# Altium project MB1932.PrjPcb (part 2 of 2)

## Sheet STLINK_V2EC.SchDoc: STLINK-V2EC
size A3; Date: Not used; ApprovedBy: Not used; CheckedBy: Not used; Author: Not used; CompanyName: STMicroelectronics; DrawnBy: Not used; Engineer: Not used; Organization: Not used; Address1: Not used; Address2: Not used; Address3: Not used; Address4: Not used; DocumentNumber: Not used; Revision: V0.1; SheetNumber: 6; SheetTotal: 7
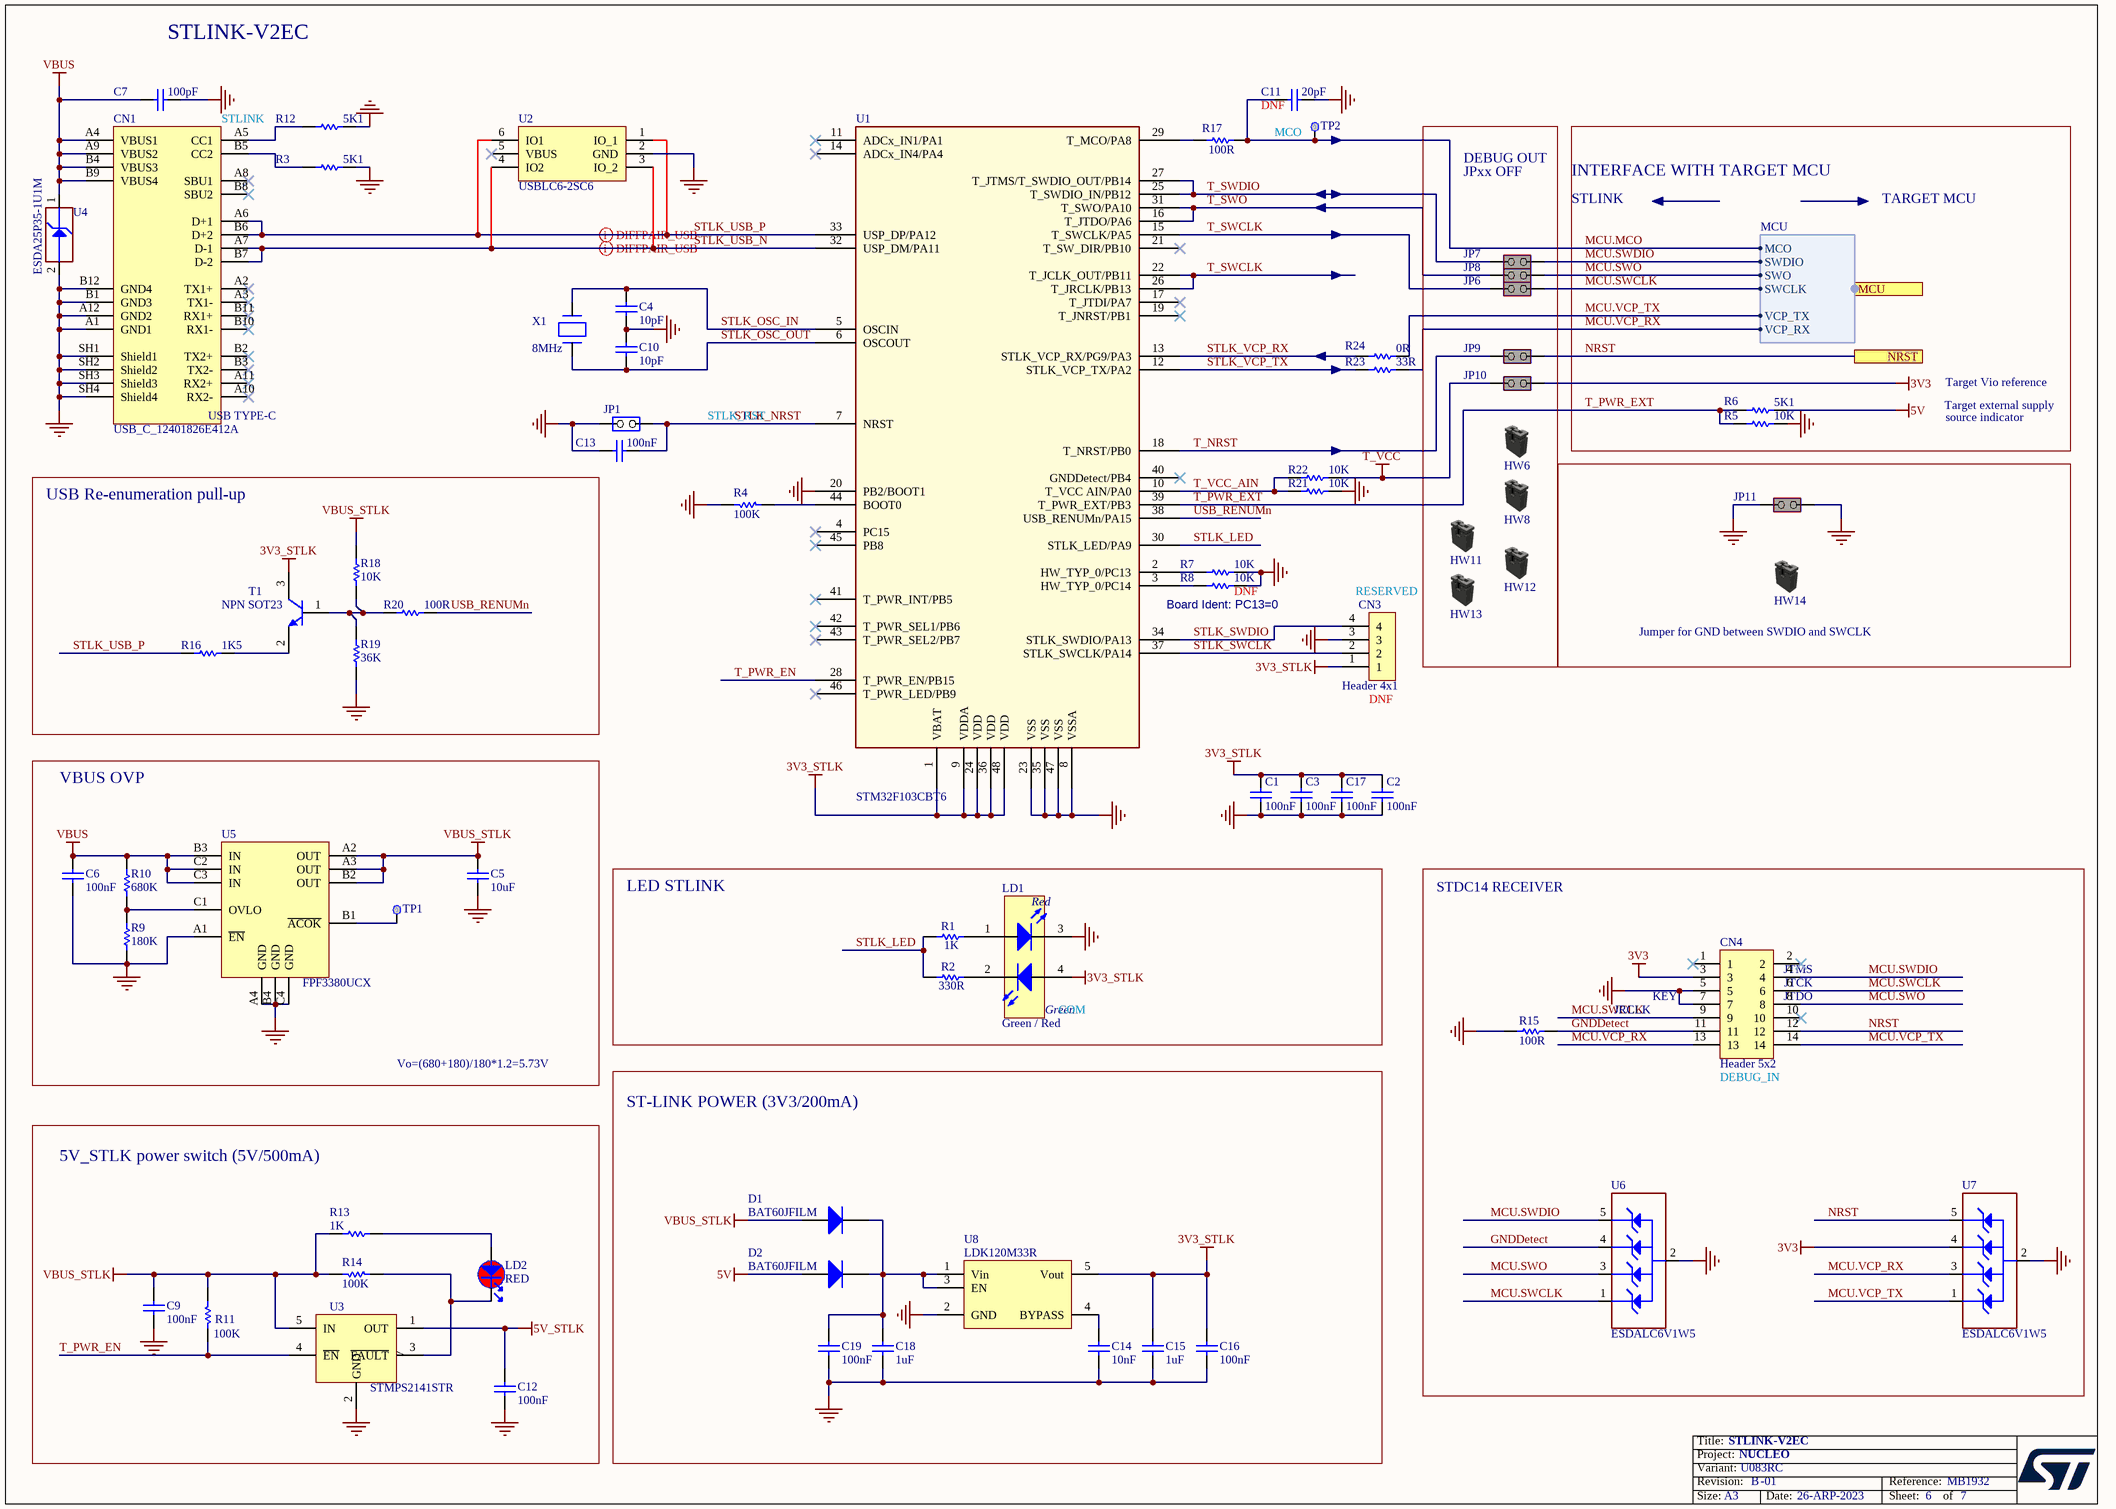
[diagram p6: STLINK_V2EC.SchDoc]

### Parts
C1  value 100nF  [C0402]  (hidden comment: Capacitor)
C2  value 100nF  [C0402]  (hidden comment: Capacitor)
C3  value 100nF  [C0402]  (hidden comment: Capacitor)
C4  value 10pF  [C0402]  (hidden comment: Capacitor)
C5  value 10uF  [C0603]  (hidden comment: Capacitor)
C6  value 100nF  [C0603]  (hidden comment: Capacitor)
C7  value 100pF  [C0402]  (hidden comment: Capacitor)
C9  value 100nF  [C0402]  (hidden comment: Capacitor)
C10  value 10pF  [C0402]  (hidden comment: Capacitor)
C11  value 20pF  [C0402]  (hidden comment: Capacitor)
C12  value 100nF  [C0402]  (hidden comment: Capacitor)
C13  value 100nF  [C0402]  (hidden comment: Capacitor)
C14  value 10nF  [C0402]  (hidden comment: Capacitor)
C15  value 1uF  [C0603]  (hidden comment: Capacitor)
C16  value 100nF  [C0402]  (hidden comment: Capacitor)
C17  value 100nF  [C0402]  (hidden comment: Capacitor)
C18  value 1uF  [C0603]  (hidden comment: Capacitor)
C19  value 100nF  [C0402]  (hidden comment: Capacitor)
CN1  value USB_C_12401826E412A  [CON_USB-TYPEC_AMPHENOL_12401826E412A]  (hidden comment: USB_TYPE_C_Receptacle)
CN3  Header 4x1  [CON_SAMTEC_TSW-104-07-G-S]
CN4  value Header 5x2  [CON_STDC14_Receiver_MEDIUM_WITH_MIPI10_3D]  (hidden comment: Header 7x2)
D1  BAT60JFILM  [DIO_SOD323]
D2  BAT60JFILM  [DIO_SOD323]
HW6  Shunt Black 2.54mm  (value not drawn)  (mechanical)
HW8  Shunt Black 2.54mm  (value not drawn)  (mechanical)
HW11  Shunt Black 2.54mm  (value not drawn)  (mechanical)
HW12  Shunt Black 2.54mm  (value not drawn)  (mechanical)
HW13  Shunt Black 2.54mm  (value not drawn)  (mechanical)
HW14  Shunt Black 2.54mm  (value not drawn)  (mechanical)
JP1  Jumper_Header 2x1  [CON_SAMTEC_TSW-102-07-G-S]  (value not drawn)
JP6  Jumper_Header 2x1 Fitted  [CON_SAMTEC_TSW-102-07-G-S]  (value not drawn)
JP7  Jumper_Header 2x1 Fitted  [CON_SAMTEC_TSW-102-07-G-S]  (value not drawn)
JP8  Jumper_Header 2x1 Fitted  [CON_SAMTEC_TSW-102-07-G-S]  (value not drawn)
JP9  Jumper_Header 2x1 Fitted  [CON_SAMTEC_TSW-102-07-G-S]  (value not drawn)
JP10  Jumper_Header 2x1 Fitted  [CON_SAMTEC_TSW-102-07-G-S]  (value not drawn)
JP11  Jumper_Header 2x1 Fitted  [CON_SAMTEC_TSW-102-07-G-S]  (value not drawn)
LD1  value Green / Red  [LED_BI-GR_WE-150141SV73110]  (hidden comment: LED_BICOLOR)
LD2  value RED  [LED_0402_KINGBRIGHT_KPHHS-1005SURCK_HYPER-RED_1A2K_H0P5]  (hidden comment: LED_red)
R1  value 1K  [R0402]  (hidden comment: Resistor)
R2  value 330R  [R0402]  (hidden comment: Resistor)
R3  value 5K1  [R0402]  (hidden comment: Resistor)
R4  value 100K  [R0402]  (hidden comment: Resistor)
R5  value 10K  [R0402]  (hidden comment: Resistor)
R6  value 5K1  [R0402]  (hidden comment: Resistor)
R7  value 10K  [R0402]  (hidden comment: Resistor)
R8  value 10K  [R0402]  (hidden comment: Resistor)
R9  value 180K  [R0402]  (hidden comment: Resistor)
R10  value 680K  [R0402]  (hidden comment: Resistor)
R11  value 100K  [R0402]  (hidden comment: Resistor)
R12  value 5K1  [R0402]  (hidden comment: Resistor)
R13  value 1K  [R0402]  (hidden comment: Resistor)
R14  value 100K  [R0402]  (hidden comment: Resistor)
R15  value 100R  [R0402]  (hidden comment: Resistor)
R16  value 1K5  [R0402]  (hidden comment: Resistor)
R17  value 100R  [R0402]  (hidden comment: Resistor)
R18  value 10K  [R0402]  (hidden comment: Resistor)
R19  value 36K  [R0402]  (hidden comment: Resistor)
R20  value 100R  [R0402]  (hidden comment: Resistor)
R21  value 10K  [R0402]  (hidden comment: Resistor)
R22  value 10K  [R0402]  (hidden comment: Resistor)
R23  value 33R  [R0402]  (hidden comment: Resistor)
R24  value 0R  [R0402]  (hidden comment: Resistor)
T1  value NPN SOT23  [NPN_SOT23]  (hidden comment: 9013-SOT23)
TP1  Test Point  [TP_SMD_1MM]  (value not drawn)  (no BOM)
TP2  Test Point  [TP_SMD_1MM]  (value not drawn)  (no BOM)
U1  value STM32F103CBT6  [ICC_LQFP48_7X7_P050]  (hidden comment: STLINK-V2EC)
U2  USBLC6-2SC6  [ESD_SOT23-6L]
U3  STMPS2141STR  [MOS_SOT23-5L]
U4  value ESDA25P35-1U1M  [ESD_QFN1610_2N_1K_2A]  (hidden comment: ESD-TRANSIL)
U5  FPF3380UCX  [ICC_WLCSP12_1P858x1P318_P040]
U6  ESDALC6V1W5  [ESD_SOT323-5L]
U7  ESDALC6V1W5  [ESD_SOT323-5L]
U8  LDK120M33R  [REG_SOT23-5L]
X1  value 8MHz  [CRY_NX3225GD_2P]  (hidden comment: XTAL_2_PINS)

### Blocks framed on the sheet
INTERFACE WITH TARGET MCU: R5 R6
USB Re-enumeration pull-up: R16 R18-R20 T1
Jumper for GND between SWDIO and SWCLK: HW14 JP11
VBUS OVP: C5 C6 R9 R10 TP1 U5
LED STLINK: LD1 R1 R2
STDC14 RECEIVER: CN4 R15 U6 U7
ST-LINK POWER (3V3/200mA): C14-C16 C18 C19 D1 D2 U8
5V_STLK power switch (5V/500mA): C9 C12 LD2 R11 R13 R14 U3

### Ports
MCU (harness MCU), NRST

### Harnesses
MCU: MCO, SWDIO, SWO, VCP_TX, SWCLK, VCP_RX

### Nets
3V3: CN4.3 JP10.1(COMMON) U7.4(IO3)
3V3_STLK: C1.1 C2.1 C3.1 C15.2 C16.2 C17.1 CN3.1 LD1.4(Green_anode) T1.3(C) U1.1(VBAT) U1.9(VDDA) U1.24(VDD) U1.36(VDD) U1.48(VDD) U8.5(Vout)
5V: D2.1(A) R6.2
5V_STLK: C12.2 U3.1(OUT)
GND: C1.2 C2.2 C3.2 C4.1 C5.1 C6.2 C7.2 C9.1 C10.2 C11.1 C12.1 C13.1 C14.1 C15.1 C16.1 C17.2 C18.1 C19.1 CN1.A1(GND1) CN1.A12(GND2) CN1.B1(GND3) CN1.B12(GND4) CN1.SH1(Shield1) CN1.SH2(Shield2) CN1.SH3(Shield3) CN1.SH4(Shield4) CN3.3 CN4.5 CN4.7 JP1.2(NO) JP11.1(COMMON) JP11.2(NO) LD1.3(RED_cathode) R3.2 R4.1 R5.2 R7.2 R8.2 R9.1 R12.2 R15.1 R19.1 R21.2 U1.8(VSSA) U1.20(PB2/BOOT1) U1.23(VSS) U1.35(VSS) U1.47(VSS) U2.2(GND) U3.2(GND) U4.2(GND) U5.A1(~{EN}) U5.A4(GND) U5.B4(GND) U5.C4(GND) U6.2(GND) U7.2(GND) U8.2(GND)
T_VCC: JP10.2(NO) R22.2
VBUS: C6.1 C7.1 CN1.A4(VBUS1) CN1.A9(VBUS2) CN1.B4(VBUS3) CN1.B9(VBUS4) R10.2 U4.1(IO1) U5.B3(IN) U5.C2(IN) U5.C3(IN)
VBUS_STLK: C5.2 C9.2 D1.1(A) R11.2 R13.2 R14.2 R18.2 U3.5(IN) U5.A2(OUT) U5.A3(OUT) U5.B2(OUT)
GNDDetect: CN4.11 R15.2 U6.4(IO3)
MCU.MCO: C11.2 R17.2 TP2.1 ; port MCU.MCO
MCU.SWCLK: CN4.6 CN4.9 JP6.1(COMMON) U6.1(IO1) ; port MCU.SWCLK
MCU.SWDIO: CN4.4 JP7.1(COMMON) U6.5(IO4) ; port MCU.SWDIO
MCU.SWO: CN4.8 JP8.1(COMMON) U6.3(IO2) ; port MCU.SWO
MCU.VCP_RX: CN4.13 R23.2 U7.3(IO2) ; port MCU.VCP_RX
MCU.VCP_TX: CN4.14 R24.2 U7.1(IO1) ; port MCU.VCP_TX
NRST: CN4.12 JP9.1(COMMON) U7.5(IO4) ; port NRST
STLK_LED: R1.2 R2.1 U1.30(STLK_LED/PA9)
STLK_NRST: C13.2 JP1.1(COMMON) U1.7(NRST)
STLK_OSC_IN: C4.2 U1.5(OSCIN) X1.2(X2)
STLK_OSC_OUT: C10.1 U1.6(OSCOUT) X1.1(X1)
STLK_SWCLK: CN3.2 U1.37(STLK_SWCLK/PA14)
STLK_SWDIO: CN3.4 U1.34(STLK_SWDIO/PA13)
STLK_USB_N: CN1.A7(D-1) CN1.B7(D-2) U1.32(USP_DM/PA11) U2.3(IO_2) U2.4(IO2)
STLK_USB_P: CN1.A6(D+1) CN1.B6(D+2) R16.1 U1.33(USP_DP/PA12) U2.1(IO_1) U2.6(IO1)
STLK_VCP_RX: R24.1 U1.13(STLK_VCP_RX/PG9/PA3)
STLK_VCP_TX: R23.1 U1.12(STLK_VCP_TX/PA2)
T_NRST: JP9.2(NO) U1.18(T_NRST/PB0)
T_PWR_EN: R11.1 U1.28(T_PWR_EN/PB15) U3.4(~{EN})
T_PWR_EXT: R5.1 R6.1 U1.39(T_PWR_EXT/PB3)
T_SWCLK: JP6.2(NO) U1.15(T_SWCLK/PA5) U1.22(T_JCLK_OUT/PB11) U1.26(T_JRCLK/PB13)
T_SWDIO: JP7.2(NO) U1.25(T_SWDIO_IN/PB12) U1.27(T_JTMS/T_SWDIO_OUT/PB14)
T_SWO: JP8.2(NO) U1.16(T_JTDO/PA6) U1.31(T_SWO/PA10)
T_VCC_AIN: R21.1 R22.1 U1.10(T_VCC_AIN/PA0)
USB_RENUMn: R20.2 U1.38(USB_RENUMn/PA15)
NetC14_2: C14.2 U8.4(BYPASS)
NetC18_2: C18.2 C19.2 D1.2(K) D2.2(K) U8.1(Vin) U8.3(EN)
NetCN1_A5: CN1.A5(CC1) R12.1
NetCN1_B5: CN1.B5(CC2) R3.1
NetLD1_1: LD1.1(Red_anode) R1.1
NetLD1_2: LD1.2(Green_cathode) R2.2
NetLD2_1: LD2.1 R13.1
NetLD2_2: LD2.2 R14.1 U3.3(~{FAULT})
NetR4_2: R4.2 U1.44(BOOT0)
NetR7_1: R7.1 U1.2(HW_TYP_0/PC13)
NetR8_1: R8.1 U1.3(HW_TYP_0/PC14)
NetR9_2: R9.2 R10.1 U5.C1(OVLO)
NetR16_2: R16.2 T1.2(E)
NetR17_1: R17.1 U1.29(T_MCO/PA8)
NetR18_1: R18.1 R19.2 R20.1 T1.1(B)
NetTP1_1: TP1.1 U5.B1(~{ACOK})

Not connected (* = marked no-connect by the designer): CN1 A2(TX1+)* A3(TX1-)* A8(SBU1)* A10(RX2-)* A11(RX2+)* B2(TX2+)* B3(TX2-)* B8(SBU2)* B10(RX1-)* B11(RX1+)*; CN4 1* 2* 10*; U1 4(PC15)* 11(ADCx_IN1/PA1)* 14(ADCx_IN4/PA4)* 17(T_JTDI/PA7)* 19(T_JNRST/PB1)* 21(T_SW_DIR/PB10)* 40(GNDDetect/PB4)* 41(T_PWR_INT/PB5)* 42(T_PWR_SEL1/PB6)* 43(T_PWR_SEL2/PB7)* 45(PB8)* 46(T_PWR_LED/PB9)*; U2 5(VBUS)*

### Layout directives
differential pair; rule Impedance Constraint [Min = 85.00    Max = 95.00    ]: STLK_USB_N, STLK_USB_P

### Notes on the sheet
- STLINK-V2EC
- (near C11) DNF
- STLINK
- MCO
- JPxx OFF
- DEBUG OUT
- TARGET MCU
- STLK_RST
- Target external supply
- Target Vio reference
- source indicator
- (near R8) Board Ident: PC13=0
- (near R8) DNF
- (near CN3) RESERVED
- (near CN3) DNF
- (near CN4) JTCK
- (near CN4) JTMS
- (near LD1) COM
- (near CN4) KEY
- (near CN4) JRCLK
- (near CN4) JTDO
- Vo=(680+180)/180*1.2=5.73V
- (near CN4) DEBUG_IN

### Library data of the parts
C1-C3 C12 C13 C17 = MCD-00006: Capacitor, MLCC, 100nF, 16V, X7R, +/-10%, 0402, T=0.5mm; Manufacturer_Part_Number: CC0402KRX7R7BB104; Manufacturer: YAGEO; Part_Preference: Recommended; Alternate_Manufacturer_Part_Number: GCM155R71C104KA55D; Alternate_Manufacturer: MURATA; Order_Code_RS: 616-9701; Component_Country_Of_Origin: China; ShowFields: YES; ID: 2474; ECCN_US: EAR99; ECCN_EU: NEC; Provided_By: SUBCO
C4 C10 = MCD-00015: Capacitor, MLCC, 10pF, 50V, NPO, +/-5%, 0402, T=0.5mm; Manufacturer_Part_Number: CC0402JRNPO9BN100; Manufacturer: YAGEO; Alternate_Manufacturer_Part_Number: GCM155R71C104KA55D; Alternate_Manufacturer: MURATA; Part_Preference: Recommended; ECCN_US: EAR99; ECCN_EU: NEC; Provided_By: SUBCO; Order_Code_RS: 616-9256; Component_Country_Of_Origin: China; ShowFields: YES; ID: 2465
C5 = MCD-00099: Capacitor, MLCC, 10uF, 10V, X5R, +/-10%, 0603, T=0.8mm; Part_Preference: Recommended; Manufacturer: MURATA; Manufacturer_Part_Number: GRM188R61A106KE69D; Order_Code_RS: 170-6168; Component_Country_Of_Origin: Japan; ShowFields: YES; ID: 2770
C6 = MCD-01099: Capacitor, MLCC, 100nF, 50V, X7R, +/-10%, 0603, T=0.8mm; Manufacturer_Part_Number: CC0603KRX7R9BB104; Manufacturer: YAGEO; Alternate_Manufacturer_Part_Number: GCM155R71C104KA55D; Alternate_Manufacturer: MURATA; BMS_Part_Number: 9142278; Part_Preference: Recommended; ECCN_US: EAR99; ECCN_EU: NEC; Provided_By: SUBCO; Order_Code_RS: 669-8767; Component_Country_Of_Origin: China; ShowFields: YES; ID: 3397
C7 = MCD-00205: Capacitor, MLCC, 100pF, 50V, NPO, +/-5%, 0402, T=0.5mm; Part_Preference: Recommended; Manufacturer: YAGEO; Manufacturer_Part_Number: CC0402JRNPO9BN101; Alternate_Manufacturer_Part_Number: GCM155R71C104KA55D; Alternate_Manufacturer: MURATA; Component_Country_Of_Origin: China; ShowFields: YES; ID: 2658; ECCN_US: EAR99; ECCN_EU: NEC; Provided_By: SUBCO
C9 = MCD-00006: Capacitor, MLCC, 100nF, 16V, X7R, +/-10%, 0402, T=0.5mm; Part_Preference: Recommended; Manufacturer: YAGEO; Manufacturer_Part_Number: CC0402KRX7R7BB104; Alternate_Manufacturer_Part_Number: GCM155R71C104KA55D; Alternate_Manufacturer: MURATA; Order_Code_RS: 616-9701; Component_Country_Of_Origin: China; ShowFields: YES; ID: 2474; ECCN_US: EAR99; ECCN_EU: NEC; Provided_By: SUBCO
C11 = MCD-00016: Capacitor, MLCC, 20pF, 50V, NPO, +/- 5%, 0402, T=0.5mm; Manufacturer_Part_Number: CC0402JRNPO9BN200; Manufacturer: YAGEO; Part_Preference: Recommended; Alternate_Manufacturer_Part_Number: GCM155R71C104KA55D; Alternate_Manufacturer: MURATA; Component_Country_Of_Origin: China; ShowFields: YES; ID: 2479; ECCN_US: EAR99; ECCN_EU: NEC; Provided_By: SUBCO
C14 = MCD-02198: Capacitor, MLCC, 10nF, 50V, X7R, +/-10%, 0402, T=0.5mm; Manufacturer_Part_Number: CC0402KRX7R9BB103; Manufacturer: YAGEO; Alternate_Manufacturer_Part_Number: GCM155R71C104KA55D; Alternate_Manufacturer: MURATA; Part_Preference: Recommended; ECCN_US: EAR99; ECCN_EU: NEC; Provided_By: SUBCO; Order_Code_RS: 6169644; Component_Country_Of_Origin: China; ShowFields: YES; ID: 4298
C15 C18 = MCD-00010: Capacitor, MLCC, 1uF, 16V, X5R, +/-10%, 0603, T=0.8mm; Manufacturer_Part_Number: CC0603KRX5R7BB105; Manufacturer: YAGEO; Alternate_Manufacturer_Part_Number: GCM155R71C104KA55D; Alternate_Manufacturer: MURATA; Part_Preference: Recommended; ECCN_US: EAR99; ECCN_EU: NEC; Provided_By: SUBCO; Component_Country_Of_Origin: China; ShowFields: YES; ID: 2470
C16 C19 = MCD-00006: Capacitor, MLCC, 100nF, 16V, X7R, +/-10%, 0402, T=0.5mm; Manufacturer_Part_Number: CC0402KRX7R7BB104; Manufacturer: YAGEO; Alternate_Manufacturer_Part_Number: GCM155R71C104KA55D; Alternate_Manufacturer: MURATA; Part_Preference: Recommended; ECCN_US: EAR99; ECCN_EU: NEC; Provided_By: SUBCO; Order_Code_RS: 616-9701; Component_Country_Of_Origin: China; ShowFields: YES; ID: 2474
CN1 = MCD-03232: USB_TypeC, 24 pins, RA, SMD, T=2.96mm (USB Certified 3.1); Part_Type: Connector; Part_Preference: Recommended; Manufacturer: AMPHENOL ICC; Manufacturer_Part_Number: 12401826E412A; Component_Country_Of_Origin: China°; ShowFields: YES; ID: 5348
CN3 = MCD-00029: Header, 4x1, 2.54mm, VR, TH, T=5.84mm/2.54mm; Manufacturer_Part_Number: TSW-104-07-G-S; Manufacturer: SAMTEC; Part_Type: Connector; Part_Preference: Recommended; Order_Code_RS: 161-2261; Component_Country_Of_Origin: China, Costa Rica, Malaysia, United States, Vietnam; ShowFields: YES; ID: 2487
CN4 = MCD-01226: Header, 5x2, 1.27mm, VR, SMD, T=5.97mm/3.05mm; Part_Type: Connector; Manufacturer_Part_Number: FTSH-105-01-L-DV-K; Manufacturer: SAMTEC; Part_Preference: Recommended; Order_Code_RS: 159-2332; Component_Country_Of_Origin: China, Costa Rica, Malaysia, United States, Vietnam; ShowFields: YES; ID: 3265
D1 D2 = MCD-00034: Part_Type: Diode; Manufacturer: STMICROELECTRONICS; BMS_Part_Number: 9151097; Part_Preference: Recommended; Manufacturer_HQ_COO: EU; ECCN_US: EAR99; ECCN_EU: NEC; Provided_By: Subcon; Initial_Board_Reference: mb1274; Component_Country_Of_Origin: China; ShowFields: YES; ID: 2483
HW6 HW8 HW11-HW14 = MCD-00043: SHUNT 2.54mm BLACK; Manufacturer_Part_Number: SNT-100-BK-G; Manufacturer: SAMTEC; Part_Type: Misc; Part_Preference: Recommended; Full_Alternate_Internal_Part_Number: MCD-02388; Value: SNT-100-BK-G; Component_Country_Of_Origin: China, Costa Rica, Malaysia, United States, Vietnam; ShowFields: YES; ID: 2551
JP1 = MCD-00045: Header, 2x1, 2.54mm, VR, TH, T=5.84mm/2.54mm; Part_Preference: Recommended; Part_Type: Connector; Manufacturer: SAMTEC; Manufacturer_Part_Number: TSW-102-07-G-S; Full_Alternate_Internal_Part_Number: MCD-02390; Order_Code_RS: 155-5312; Component_Country_Of_Origin: China, Costa Rica, Malaysia, United States, Vietnam; ShowFields: YES; ID: 2545
JP6-JP11 = MCD-00683: Header, 2x1, 2.54mm, VR, TH, T=5.84mm/2.54mm; Part_Type: Connector; Manufacturer_Part_Number: TSW-102-07-G-S; Manufacturer: SAMTEC; Alternate_Manufacturer_Part_Number: 313102S111116; Alternate_Manufacturer: LIANYI; Part_Preference: Recommended; Full_Alternate_Internal_Part_Number: MCD-02389; Partial_Alternate_Internal_Part_Number: MCD-02957; Provided_By: SUBCO; Order_Code_RS: 155-5312; Component_Country_Of_Origin: China, Costa Rica, Malaysia, United States, Vietnam; ShowFields: YES; ID: 3057
LD1 = MCD-02631: LED Bicolor, Green/Red, 2V, 20mA,  4-PLCC; Part_Type: Display; Part_Preference: Recommended; Manufacturer: WURTH ELEKTRONIK; Manufacturer_Part_Number: 150141SV73110; Order_Code_RS: 184-6963; Component_Country_Of_Origin: China; ShowFields: YES; ID: 4737
LD2 = MCD-00708: LED 0402 Red; Part_Type: Display; Manufacturer_Part_Number: KPHHS-1005SURCK; Manufacturer: KINGBRIGHT; Alternate_Manufacturer_Part_Number: LS Q976-NR-1; Alternate_Manufacturer: OSRAM OPTO SEMICONDUCTORS; Part_Preference: Recommended; Provided_By: SUBCO; Component_Country_Of_Origin: Unknown; ShowFields: YES; ID: 3037
R1 = MCD-00061: Resistor, 1K, 0402, +/-1%,1/16W; Part_Preference: Recommended; Manufacturer: YAGEO; Manufacturer_Part_Number: RC0402FR-071KL; Alternate_Manufacturer_Part_Number: RT0402FRE07100KL; ShowFields: YES; ID: 2532; ECCN_US: EAR99; ECCN_EU: NEC; Provided_By: SUBCO; Component_Country_Of_Origin: China
R2 = MCD-00062: Resistor, 330R, 0402, +/-1%, 1/16W; Part_Preference: Recommended; Manufacturer: YAGEO; Manufacturer_Part_Number: RC0402FR-07330RL; Alternate_Manufacturer_Part_Number: RT0402FRE07100KL; Component_Country_Of_Origin: China; ShowFields: YES; ID: 2529; ECCN_US: EAR99; ECCN_EU: NEC; Provided_By: SUBCO
R3 R6 R12 = MCD-00333: Resistor, 5K1, 0402, +/-1%, 1/16W; Part_Preference: Recommended; Manufacturer: YAGEO; Manufacturer_Part_Number: RC0402FR-075K1L; Alternate_Manufacturer_Part_Number: RT0402FRE07100KL; Component_Country_Of_Origin: China; ShowFields: YES; ID: 2944; ECCN_US: EAR99; ECCN_EU: NEC; Provided_By: SUBCO
R4 R11 R14 = MCD-00059: Resistor, 100K, 0402, +/-1%, 1/16W; Manufacturer_Part_Number: RC0402FR-07100KL; Manufacturer: YAGEO; Part_Preference: Recommended; Alternate_Manufacturer_Part_Number: RT0402FRE07100KL; Component_Country_Of_Origin: China; ShowFields: YES; ID: 2533; ECCN_US: EAR99; ECCN_EU: NEC; Provided_By: SUBCO
R5 R7 R8 R21 R22 = MCD-00053: Resistor, 10K, 0402, +/-1%, 1/16W; Manufacturer_Part_Number: RC0402FR-0710KL; Manufacturer: YAGEO; BMS_Part_Number: 9131590; Part_Preference: Recommended; Alternate_Manufacturer_Part_Number: RT0402FRE07100KL; Component_Country_Of_Origin: China; ShowFields: YES; ID: 2539; ECCN_US: EAR99; ECCN_EU: NEC; Provided_By: SUBCO
R9 = MCD-00413: Resistor, 180K, 0402, +/-1%, 1/16W; Manufacturer_Part_Number: RC0402FR-07180KL; Manufacturer: YAGEO; Part_Preference: Recommended; Component_Country_Of_Origin: China; ShowFields: YES; ID: 2864
R10 = MCD-00513: Resistor, 680K, 0402, +/-1%, 1/16W; Manufacturer_Part_Number: RC0402FR-07680KL; Manufacturer: YAGEO; Alternate_Manufacturer_Part_Number: RT0402FRE07100KL; Part_Preference: Recommended; ECCN_US: EAR99; ECCN_EU: NEC; Provided_By: SUBCO; Component_Country_Of_Origin: China; ShowFields: YES; ID: 3227
R13 = MCD-00061: Resistor, 1K, 0402, +/-1%,1/16W; Manufacturer_Part_Number: RC0402FR-071KL; Manufacturer: YAGEO; Alternate_Manufacturer_Part_Number: RT0402FRE07100KL; Part_Preference: Recommended; ECCN_US: EAR99; ECCN_EU: NEC; Provided_By: SUBCO; Component_Country_Of_Origin: China; ShowFields: YES; ID: 2532
R15 R17 = MCD-00067: Resistor, 100R, 0402, +/- 1%, 1/16W; Part_Preference: Recommended; Manufacturer: YAGEO; Manufacturer_Part_Number: RC0402FR-07100RL; Alternate_Manufacturer_Part_Number: RT0402FRE07100KL; Component_Country_Of_Origin: China; ShowFields: YES; ID: 2527; ECCN_US: EAR99; ECCN_EU: NEC; Provided_By: SUBCO
R16 = MCD-00068: Resistor, 1K5, 0402, +/-1%, 1/16W; Manufacturer_Part_Number: RC0402FR-071K5L; Manufacturer: YAGEO; Alternate_Manufacturer_Part_Number: RT0402FRE07100KL; Part_Preference: Recommended; ECCN_US: EAR99; ECCN_EU: NEC; Provided_By: SUBCO; Component_Country_Of_Origin: China; ShowFields: YES; ID: 2524
R18 = MCD-00053: Resistor, 10K, 0402, +/-1%, 1/16W; Manufacturer_Part_Number: RC0402FR-0710KL; Manufacturer: YAGEO; Alternate_Manufacturer_Part_Number: RT0402FRE07100KL; Part_Preference: Recommended; BMS_Part_Number: 9131590; ECCN_US: EAR99; ECCN_EU: NEC; Provided_By: SUBCO; Component_Country_Of_Origin: China; ShowFields: YES; ID: 2539
R19 = MCD-00069: Resistor, 36K, 0402, +/-1%, 1/16W; Manufacturer_Part_Number: RC0402FR-0736KL; Manufacturer: YAGEO; Alternate_Manufacturer_Part_Number: RT0402FRE07100KL; Part_Preference: Recommended; ECCN_US: EAR99; ECCN_EU: NEC; Provided_By: SUBCO; Component_Country_Of_Origin: China; ShowFields: YES; ID: 2523
R20 = MCD-00067: Resistor, 100R, 0402, +/- 1%, 1/16W; Manufacturer_Part_Number: RC0402FR-07100RL; Manufacturer: YAGEO; Alternate_Manufacturer_Part_Number: RT0402FRE07100KL; Part_Preference: Recommended; ECCN_US: EAR99; ECCN_EU: NEC; Provided_By: SUBCO; Component_Country_Of_Origin: China; ShowFields: YES; ID: 2527
R23 = MCD-00455: Resistor, 33R, 0402, +/-1%, 1/16W; Part_Preference: Recommended; Manufacturer: YAGEO; Manufacturer_Part_Number: RC0402FR-0733RL; Alternate_Manufacturer_Part_Number: RT0402FRE07100KL; Component_Country_Of_Origin: China; ShowFields: YES; ID: 2821; ECCN_US: EAR99; ECCN_EU: NEC; Provided_By: SUBCO
R24 = MCD-00052: Resistor, 0R, 0402, +/-5%, 1/16W; Part_Preference: Recommended; Manufacturer: YAGEO; Manufacturer_Part_Number: RC0402JR-070RL; Alternate_Manufacturer_Part_Number: RT0402FRE07100KL; Order_Code_RS: 618-5804; Component_Country_Of_Origin: China; ShowFields: YES; ID: 2540; ECCN_US: EAR99; ECCN_EU: NEC; Provided_By: SUBCO
T1 = MCD-00073: NPN Bipolar Transistor; Part_Type: IC; Manufacturer_Part_Number: BSR14; Manufacturer: ON SEMICONDUCTOR; Part_Preference: Recommended; ECCN_US: EAR99; ECCN_EU: NEC; Provided_By: Subcon; Initial_Board_Reference: mb1274; Component_Country_Of_Origin: Unknown; ShowFields: YES; ID: 2519
TP1 TP2 = MCD-00074: Test Point 1mm; Part_Type: Misc; Part_Preference: Recommended; ShowFields: YES; ID: 2518
U1 = MCD-03056: Medium-density performance line ARM-based 32-bit MCU with 128KB Flash; Part_Type: IC; Part_Preference: Recommended; Manufacturer: STMICROELECTRONICS; ShowFields: YES; ID: 5172; Component_Country_Of_Origin: Malaysia
U2 = MCD-00163: Very low capacitance ESD protection; Part_Type: IC; Manufacturer: STMICROELECTRONICS; BMS_Part_Number: 9151075; Part_Preference: Recommended; Manufacturer_HQ_COO: EU
U3 = MCD-00083: Enhanced single channel power switches with active low enable pin; Part_Type: IC; Manufacturer: STMICROELECTRONICS; BMS_Part_Number: 9159003; Part_Preference: Recommended; Manufacturer_HQ_COO: EU; Component_Country_Of_Origin: Malaysia; ShowFields: YES; ID: 2509
U4 = MCD-01207: High power Transient voltage suppressor:25V/35A EOS and ESD transients protection.; Part_Type: Diode; Manufacturer: STMICROELECTRONICS; BMS_Part_Number: 9179045; Part_Preference: Recommended; Manufacturer_HQ_COO: EU; Component_Country_Of_Origin: China; ShowFields: YES; ID: 3289; ECCN_US: EAR99; ECCN_EU: NEC; Provided_By: SUBCO with ST control
U5 = MCD-03166: 28 V / 5 A Rated OVP with Low On-resistance and Integrated TVS; Part_Type: IC; Part_Preference: Recommended; Manufacturer: ON_SEMICONDUCTOR; Partial_Alternate_Internal_Part_Number: MCD-03058; ShowFields: YES; ID: 5282; Alternate_EMS: AWINIC
U6 U7 = MCD-00136: Dual Transil array for ESD protection; BMS_Part_Number: 9151112; Part_Type: Diode; Part_Preference: Recommended; Manufacturer: STMICROELECTRONICS; Manufacturer_HQ_COO: EU; Component_Country_Of_Origin: China; ShowFields: YES; ID: 2731
U8 = MCD-00663: 200 mA low quiescent current very low noise LDO; Part_Type: IC; Manufacturer: STMICROELECTRONICS; BMS_Part_Number: 9176330; Part_Preference: Recommended; Manufacturer_HQ_COO: EU; Component_Country_Of_Origin: China; ShowFields: YES; ID: 3082
X1 = MCD-00092: Crystal, 8MHz, 8pF, +/-20ppm, 500R, 3.2x2.5mm; Part_Type: Crystal_Osc; Manufacturer_Part_Number: NX3225GD-8MHZ-EXS00A-CG04874; Manufacturer: NDK; BMS_Part_Number: 9157029; Part_Preference: Recommended; ECCN_US: EAR99; ECCN_EU: NEC; Provided_By: SUBCO; Component_Country_Of_Origin: Unknown; ShowFields: YES; ID: 2776

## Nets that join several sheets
3V3: Power (JP5.2 SB1.2), Arduino_Morpho_connectors (5 pins), STLINK_V2EC (CN4.3 JP10.1 U7.4)
5V: Power (9 pins), Arduino_Morpho_connectors (CN6.5 CN7.18), STLINK_V2EC (D2.1 R6.2)
5V_STLK: Power (JP4.1), STLINK_V2EC (C12.2 U3.1)
5V_VIN: Power (C22.2 JP4.3 U11.2 U11.4), Arduino_Morpho_connectors (R26.1)
AGND: STM32_microcontroller_IOs (C38.1 C39.2 SB36.2 U13.12), Arduino_Morpho_connectors (C26.1 CN5.7 CN10.9 CN10.32)
AVDD: STM32_microcontroller_IOs (7 pins), Arduino_Morpho_connectors (C26.2 SB9.2)
E5V: Power (JP4.5), Arduino_Morpho_connectors (CN7.6)
GND: Power (11 pins), STM32_microcontroller_IOs (27 pins), Arduino_Morpho_connectors (13 pins), STLINK_V2EC (58 pins)
VBAT/VLCD/VDD: STM32_microcontroller_IOs (C31.1 SB2.2 U13.1), Arduino_Morpho_connectors (CN7.33)
VBUS_STLK: Power (JP4.7), Arduino_Morpho_connectors (CN10.8), STLINK_V2EC (11 pins)
VDD: Power (JP5.1), STM32_microcontroller_IOs (12 pins), Arduino_Morpho_connectors (CN7.5)
VIN: Power (C25.2 U11.3), Arduino_Morpho_connectors (CN6.8 CN7.24)
BOOT0: STM32_microcontroller_IOs (R31.1 U13.60), Arduino_Morpho_connectors (CN7.7)
MCU.MCO: STM32_microcontroller_IOs (SB27.1), STLINK_V2EC (C11.2 R17.2 TP2.1)
MCU.SWCLK: STM32_microcontroller_IOs (U13.49), Arduino_Morpho_connectors (SB17.1), STLINK_V2EC (CN4.6 CN4.9 JP6.1 U6.1)
MCU.SWDIO: STM32_microcontroller_IOs (U13.46), Arduino_Morpho_connectors (SB15.1), STLINK_V2EC (CN4.4 JP7.1 U6.5)
MCU.SWO: STM32_microcontroller_IOs (U13.55), Arduino_Morpho_connectors (CN9.4 CN10.31), STLINK_V2EC (CN4.8 JP8.1 U6.3)
MCU.VCP_RX: STM32_microcontroller_IOs (SB8.2 SB45.2 U13.17), STLINK_V2EC (CN4.13 R23.2 U7.3)
MCU.VCP_TX: STM32_microcontroller_IOs (SB48.2 U13.16), STLINK_V2EC (CN4.14 R24.2 U7.1)
NRST: STM32_microcontroller_IOs (5 pins), Arduino_Morpho_connectors (CN6.3 CN7.14), STLINK_V2EC (CN4.12 JP9.1 U7.5)
PA0: STM32_microcontroller_IOs (U13.14), Arduino_Morpho_connectors (CN7.28 CN8.1)
PA1: STM32_microcontroller_IOs (U13.15), Arduino_Morpho_connectors (CN7.30 CN8.2)
PA2: STM32_microcontroller_IOs (SB48.1), Arduino_Morpho_connectors (CN9.2 CN10.35 SB23.2)
PA3: STM32_microcontroller_IOs (SB45.1 SB50.2), Arduino_Morpho_connectors (CN9.1 CN10.37 SB44.2)
PA4: STM32_microcontroller_IOs (U13.20), Arduino_Morpho_connectors (CN7.32 CN8.3)
PA5: STM32_microcontroller_IOs (U13.21), Arduino_Morpho_connectors (SB42.2 SB43.1)
PA6: STM32_microcontroller_IOs (U13.22), Arduino_Morpho_connectors (SB14.1 SB34.2)
PA7: STM32_microcontroller_IOs (U13.23), Arduino_Morpho_connectors (SB18.1 SB32.2)
PA8: STM32_microcontroller_IOs (U13.41), Arduino_Morpho_connectors (CN9.8 CN10.23)
PA9: STM32_microcontroller_IOs (U13.42), Arduino_Morpho_connectors (CN5.1 CN10.21 SB23.1)
PA10: STM32_microcontroller_IOs (U13.43), Arduino_Morpho_connectors (CN9.3 CN10.33 SB44.1)
PA11: STM32_microcontroller_IOs (U13.44), Arduino_Morpho_connectors (CN10.14)
PA12: STM32_microcontroller_IOs (U13.45), Arduino_Morpho_connectors (CN10.12)
PA15: STM32_microcontroller_IOs (U13.50), Arduino_Morpho_connectors (CN7.17)
PB0: STM32_microcontroller_IOs (U13.26), Arduino_Morpho_connectors (CN7.34 CN8.4)
PB1: STM32_microcontroller_IOs (SB25.2), Arduino_Morpho_connectors (CN10.24)
PB2: STM32_microcontroller_IOs (U13.28), Arduino_Morpho_connectors (CN10.22)
PB4: STM32_microcontroller_IOs (U13.56), Arduino_Morpho_connectors (CN9.6 CN10.27)
PB5: STM32_microcontroller_IOs (U13.57), Arduino_Morpho_connectors (CN9.5 CN10.29)
PB6: STM32_microcontroller_IOs (U13.58), Arduino_Morpho_connectors (CN5.3 CN10.17)
PB7: STM32_microcontroller_IOs (U13.59), Arduino_Morpho_connectors (CN7.21)
PB8: STM32_microcontroller_IOs (U13.61), Arduino_Morpho_connectors (CN5.10 CN10.3 SB51.2)
PB9: STM32_microcontroller_IOs (U13.62), Arduino_Morpho_connectors (CN5.9 CN10.5 SB47.2)
PB10: STM32_microcontroller_IOs (U13.29), Arduino_Morpho_connectors (CN9.7 CN10.25)
PB11: STM32_microcontroller_IOs (C41.1 U13.30), Arduino_Morpho_connectors (CN10.18)
PB12: STM32_microcontroller_IOs (SB20.2), Arduino_Morpho_connectors (CN10.16)
PB13: STM32_microcontroller_IOs (SB39.2), Arduino_Morpho_connectors (SB40.2 SB41.2)
PB14: STM32_microcontroller_IOs (SB35.2 SB38.2), Arduino_Morpho_connectors (SB16.2 SB37.2)
PB15: STM32_microcontroller_IOs (SB30.2 SB33.2), Arduino_Morpho_connectors (SB19.2 SB29.2)
PC0: STM32_microcontroller_IOs (U13.8), Arduino_Morpho_connectors (SB52.1)
PC1: STM32_microcontroller_IOs (U13.9), Arduino_Morpho_connectors (SB46.1)
PC2: STM32_microcontroller_IOs (U13.10), Arduino_Morpho_connectors (CN7.35)
PC3: STM32_microcontroller_IOs (U13.11), Arduino_Morpho_connectors (CN7.37)
PC4: STM32_microcontroller_IOs (U13.24), Arduino_Morpho_connectors (CN10.34)
PC5: STM32_microcontroller_IOs (U13.25), Arduino_Morpho_connectors (CN10.6)
PC6: STM32_microcontroller_IOs (U13.37), Arduino_Morpho_connectors (CN10.4)
PC7: STM32_microcontroller_IOs (U13.38), Arduino_Morpho_connectors (CN5.2 CN10.19)
PC8: STM32_microcontroller_IOs (U13.39), Arduino_Morpho_connectors (CN10.2)
PC9: STM32_microcontroller_IOs (U13.40), Arduino_Morpho_connectors (CN10.1)
PC10: STM32_microcontroller_IOs (U13.51), Arduino_Morpho_connectors (CN7.1)
PC11: STM32_microcontroller_IOs (U13.52), Arduino_Morpho_connectors (CN7.2)
PC12: STM32_microcontroller_IOs (U13.53), Arduino_Morpho_connectors (CN7.3)
PC13: STM32_microcontroller_IOs (SB3.2 U13.2), Arduino_Morpho_connectors (CN7.23)
PC14: STM32_microcontroller_IOs (R34.2 U13.3), Arduino_Morpho_connectors (SB22.1)
PC15: STM32_microcontroller_IOs (R35.2 U13.4), Arduino_Morpho_connectors (SB24.1)
PD2: STM32_microcontroller_IOs (U13.54), Arduino_Morpho_connectors (CN7.4)
PD8: STM32_microcontroller_IOs (SB11.2), Arduino_Morpho_connectors (CN10.10)
PF0: STM32_microcontroller_IOs (R36.2 SB27.2 U13.5), Arduino_Morpho_connectors (SB28.1)
PF1: STM32_microcontroller_IOs (R37.2 U13.6), Arduino_Morpho_connectors (SB31.1)
PF4: STM32_microcontroller_IOs (SB53.2), Arduino_Morpho_connectors (CN10.38)
PF5: STM32_microcontroller_IOs (SB49.1), Arduino_Morpho_connectors (CN10.36)
PF6: STM32_microcontroller_IOs (SB10.2), Arduino_Morpho_connectors (CN7.9)
PF7: STM32_microcontroller_IOs (SB13.1), Arduino_Morpho_connectors (CN7.11)

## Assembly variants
U083RC: not fitted C11 C26 C30 C33 C35 C36 C41 C42 CN3 HW7 R8 R32 R33 R36 R37 SB8 SB10 SB11 SB13 SB15 SB16 SB17 SB19 SB21 SB22 SB23 SB24 SB26 SB27 SB32 SB33 SB34 SB38 SB41 SB42 SB44 SB45 SB47 SB48 SB49 SB50 SB51 SB53 X3
L496RG: not fitted C11 C26 C30 C33 C35 C36 C41 C42 CN3 HW7 R8 R32 R33 R36 R37 SB8 SB10 SB11 SB13 SB15 SB16 SB17 SB19 SB21 SB22 SB23 SB24 SB26 SB27 SB32 SB33 SB34 SB38 SB41 SB42 SB44 SB45 SB47 SB48 SB49 SB50 SB51 SB53 X3
U031R8: not fitted C11 C26 C30 C33 C35 C36 C41 C42 CN3 HW7 R8 R32 R33 R36 R37 SB8 SB10 SB11 SB13 SB15 SB16 SB17 SB19 SB21 SB22 SB23 SB24 SB26 SB27 SB32 SB33 SB34 SB38 SB41 SB42 SB44 SB45 SB47 SB48 SB49 SB50 SB51 SB53 X3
